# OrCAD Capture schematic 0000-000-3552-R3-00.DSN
size A4; title: Add-On Board; rev: 3.00; company: Gerwin Folmer / PvdH; note: 0000-000-3552; note: Halfgeleiderweg 6; note: 6534 AV  Nijmegen
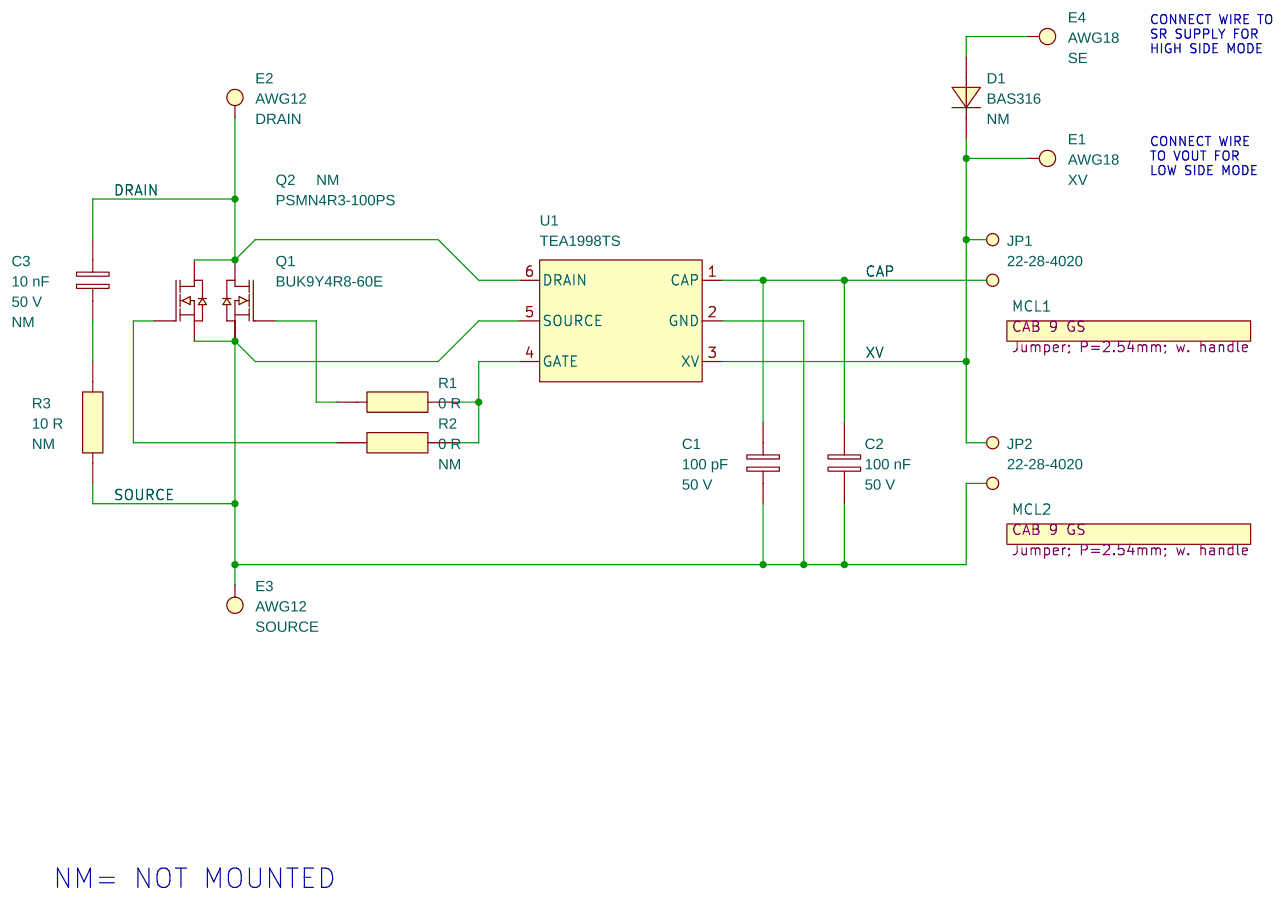
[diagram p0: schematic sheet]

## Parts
C1  100 pF  [CAPC2013X145X115Y145C180N]
C2  100 nF  [CAPC2013X145X115Y145C180N]
C3  10 nF  [CAPC2013X145X115Y145C180N]
D1  BAS316  [SOD2513X110X50Y90C260N]
E1  AWG18  [WH_AWG18_0160_0100_0220]
E2  AWG12  [WH_AWG12_0400_0200_0440]
E3  AWG12  [WH_AWG12_0400_0200_0440]
E4  AWG18  [WH_AWG18_0160_0100_0220]
JP1  22-28-4020  [CONT_MOL_22-28-4020_2PMS_L_ISO]
JP2  22-28-4020  [CONT_MOL_22-28-4020_2PMS_L_ISO]
MCL1  Jumper; P=2.54mm; w. handle
MCL2  Jumper; P=2.54mm; w. handle
Q1  BUK9Y4R8-60E  [TO127P600X120-5X60Y162C372N]
Q2  PSMN4R3-100PS  [TO220RRV254W85P3L1065T485H1960TB_AT1_ISO]
R1  0 R  [RESC3216X75X180Y115C300N]
R2  0 R  [RESC3216X75X180Y115C300N]
R3  10 R  [RESC2013X84X145Y95C200N]
U1  TEA1998TS  [SOT95P275X110-6X115Y50C260N]

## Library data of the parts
C1 = CAPN_02_01_A: Capacitor; 100 pF; 10 %; 50 V; C0G; 0805; Case: 0805; Dielectricum: C0G; HEIGHT: 1.45; Manufacturer: Any Manufacturer; Manufacturer Part Number: Any Man. Part Number; Supplier: Any Supplier; Supplier Code: Any Supp. Code; Tolerance: 10 %; Voltage: 50 V
C2 = CAPN_02_01_A: Capacitor; 100 nF; 10 %; 50 V; X7R; 0805; Case: 0805; Dielectricum: X7R; HEIGHT: 1.45; Manufacturer: Any Manufacturer; Manufacturer Part Number: Any Man. Part Number; Supplier: Any Supplier; Supplier Code: Any Supp. Code; Tolerance: 10 %; Unique Part name: CAPN_XXX_100N_50V0_10T_X7R_0805; Voltage: 50 V
C3 = CAPN_02_01_A: Capacitor; 10 nF; 10 %; 50 V; X7R; 0805; Case: 0805; Dielectricum: X7R; HEIGHT: 1.45; Manufacturer: Any Manufacturer; Manufacturer Part Number: Any Man. Part Number; Mounted: NM; Supplier: Any Supplier; Supplier Code: Any Supp. Code; Tolerance: 10 %; Unique Part name: CAPN_XXX_10N0_50V0_10T_X7R_0805; Voltage: 50 V
D1 = DIO_02_01_A: Diode; 100 V; 250 mA; Current: 250 mA; HEIGHT: 1.10; Manufacturer: NXP; Mounted: NM; Supplier: Farnell; Supplier Code: 8734275; Time Reverse Recovery: 4 ns; Unique Part name: DIO_NXP_BAS316_SC76; Voltage: 100 V
E1 = WH_01_01_A: Wirehole; AWG18; 1mm; Manufacturer: N.L.C.; Manufacturer Part Number: N.L.C.; Supplier: N.L.C.; Supplier Code: N.L.C.; Wiretext: XV
E2 = WH_01_01_A: Wirehole; AWG12; 2mm; Manufacturer: N.L.C.; Manufacturer Part Number: N.L.C.; Supplier: N.L.C.; Supplier Code: N.L.C.; Wiretext: DRAIN
E3 = WH_01_01_A: Wirehole; AWG12; 2mm; Manufacturer: N.L.C.; Manufacturer Part Number: N.L.C.; Supplier: N.L.C.; Supplier Code: N.L.C.; Wiretext: SOURCE
E4 = WH_01_01_A: Wirehole; AWG18; 1mm; Manufacturer: N.L.C.; Manufacturer Part Number: N.L.C.; Supplier: N.L.C.; Supplier Code: N.L.C.; Wiretext: SE
JP1 JP2 = JMP_02_01_B_NO-NR: Header; Straight; 1x2-way; 2.54mm; HEIGHT: 8.63; Manufacturer: Molex; Supplier: Farnell; Supplier Code: 1550559; Unique Part name: CONT_MOL_22-28-4020_2PMS_L
MCL1 MCL2 = Mechanical_Part: Manufacturer: Fischer; Manufacturer Part Number: CAB 9 GS; Supplier: Farnell; Supplier Code: 9728996
Q1 = MFN_05_01_A: MOSFET-N; 60 V; 100 A; HEIGHT: 1.20; Manufacturer: NXP; Supplier: Farnell; Supplier Code: 2319941; Voltage: 60 V
Q2 = MFN_03_01_A: MOSFET-N; 100 V; 120 A; HEIGHT: 20.75; Manufacturer: NXP; Manufacturer Part Number: PSMN4R3-100PS,127; Mounted: NM; Supplier: Digi-Key; Supplier Code: 568-8595-5-ND; Voltage: 100 V
R1 = RES_02_01_A: Resistor; 0 O; jumper; 250 mW; 1206; Case: 1206; HEIGHT: 0.75; Manufacturer: Any Manufacturer; Manufacturer Part Number: Any Man. Part Number; Supplier: Any Supplier; Supplier Code: Any Supp. Code; Tolerance: jumper; Unique Part name: RES_XXX_0R00_JMP_0W25_1206; Wattage: 250 mW
R2 = RES_02_01_A: Resistor; 0 O; jumper; 250 mW; 1206; Case: 1206; HEIGHT: 0.75; Manufacturer: Any Manufacturer; Manufacturer Part Number: Any Man. Part Number; Mounted: NM; Supplier: Any Supplier; Supplier Code: Any Supp. Code; Tolerance: jumper; Unique Part name: RES_XXX_0R00_JMP_0W25_1206; Wattage: 250 mW
R3 = RES_02_01_A: Resistor; 10 O; 1 %; 100 mW; 0805; Case: 0805; HEIGHT: 0.65; Manufacturer: Any Manufacturer; Manufacturer Part Number: Any Man. Part Number; Mounted: NM; Supplier: Any Supplier; Supplier Code: Any Supp. Code; Tolerance: 1 %; Unique Part name: RES_XXX_10R0_1T0_0W10_0805; Wattage: 100 mW
U1 = NXP_TEA1993_TSOP6: Sync. Rec. Ctrl.; TEA1998TS; Manufacturer: NXP; Supplier: NXP; Supplier Code: Customer Delivers Component

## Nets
CAP: C1.1 C2.1 JP1.2 U1.1(CAP)
DRAIN: C3.1 E2.1 Q1.5(D) Q2.2(D) U1.6(DRAIN)
SOURCE: C1.2 C2.2 E3.1 JP2.2 Q1.1(S1) Q1.2(S2) Q1.3(S3) Q2.3(S) R3.1 U1.2(GND) U1.5(SOURCE)
XV: D1.1(C) E1.1 JP1.1 JP2.1 U1.3(XV)
N6706455: Q1.4(G) R1.1
N6706664: R1.2 R2.2 U1.4(GATE)
N6708555: C3.2 R3.2
N6709881: Q2.1(G) R2.1
N6711825: D1.2(A) E4.1

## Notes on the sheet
- CONNECT WIRE TO
  SR SUPPLY FOR
  HIGH SIDE MODE
- CONNECT WIRE
  TO VOUT FOR
  LOW SIDE MODE
- NM= NOT MOUNTED
